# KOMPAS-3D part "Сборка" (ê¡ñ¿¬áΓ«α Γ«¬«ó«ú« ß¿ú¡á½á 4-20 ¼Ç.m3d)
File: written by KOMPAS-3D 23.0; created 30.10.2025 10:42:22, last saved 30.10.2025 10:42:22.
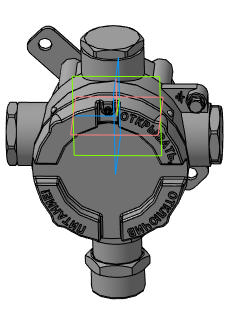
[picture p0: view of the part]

Document properties: Полное имя файла: D:\Users\5322\Documents\КОМПАС\Рабочая\Индикатор токового сигнала 4-20 мА ВУУК ИТС(3-277)\3D\Индикатор токового сигнала 4-20 мА.m3d

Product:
- Part/product: Сборка
    Масса: 1.775804
  - Component [assembly]: Сборка плата  | qty 1  | Масса: 0.276871; source file: Сборка плата.a3d
  - Component [detail]: Стойка  | qty 2  | Материал: ЛС 59-1  ГОСТ 15527-70 (density 8500 kg/m3); Масса: 0.005519; source file: Стойка.m3d
  - Component [detail]: Смотровое стекло  | qty 1  | Материал: Стекло органическое СО-120-А ГОСТ 10667-90 (density 0 kg/m3); source file: Смотровое стекло.m3d
  - Component [detail]: Деталь  | qty 1  | Масса: 0.011643; source file: ..\..\Корпус КРВ\Шильдик-1.m3d
  - Component [standard]: Гайка М4-6H ГОСТ 5915-70  | qty 2  | pos. 1  | Масса: 0.0008; Раздел спецификации: Стандартные изделия
  - Component [standard]: Шпилька М4-6gx22 ГОСТ 22042-76  | qty 1  | pos. 1  | Масса: 0.001706; Раздел спецификации: Стандартные изделия
  - Component [standard]: Шайба C.4.37 ГОСТ 11371-78  | qty 2  | pos. 1  | Материал: АД1 ГОСТ 4784-97 (density 1000 kg/m3); Масса: 0.000299; Раздел спецификации: Стандартные изделия
  - Component [standard]: Шайба 4Л ГОСТ 6402-70  | qty 1  | pos. 1  | Масса: 0.000125; Раздел спецификации: Стандартные изделия
  - Component [standard]: Hexagon socket set screw ISO 4026-М4 x 12-45H  | qty 1  | pos. 1
      Материал: Steel (density 1000 kg/m3)
      Масса: 0.00086
      Раздел спецификации: Стандартные изделия
      Организация: Ascon
      Автор: Constantine
      additional columns: М4 x 12 - 45H
  - Component [standard]: Винт А .М5-6gx8 ГОСТ 17475-80  | qty 1  | pos. 1  | Масса: 0.001391; Раздел спецификации: Стандартные изделия; Автор: Канунников Олег; additional columns: А.М5-6gx8
  - Component [standard]: Винт А.М 5-6g x 8 ГОСТ 17475-80  | qty 1  | pos. 1  | Масса: 0.001391; Раздел спецификации: Стандартные изделия; Автор: Канунников Олег; additional columns: А.М5-6gx8
  - Component [detail]: Кронштейн  | designation СЕНС.741124.906  | qty 1  | Масса: 0.056348; source file: ..\..\Корпус КРВ\Пластина крепежная.m3d
  - Component [standard]: Шайба 5Л ГОСТ 6402-70  | qty 1  | pos. 1  | Масса: 0.000186; Раздел спецификации: Стандартные изделия
  - Component [standard]: Шайба C.5.37 ГОСТ 11371-78  | qty 1  | pos. 1  | Материал: АД1 ГОСТ 4784-97 (density 1000 kg/m3); Масса: 0.00043; Раздел спецификации: Стандартные изделия
  - Component [standard]: Шайба C. 5.37 ГОСТ 11371-78  | qty 1  | pos. 1  | Материал: АД1 ГОСТ 4784-97 (density 1000 kg/m3); Масса: 0.00043; Раздел спецификации: Стандартные изделия; additional columns: C.5.37
  - Component [standard]: Болт DIN 933 - М5 х 16 - А2-70  | qty 1  | pos. 1  | Масса: 0.0036; Раздел спецификации: Стандартные изделия; additional columns: М5-6gx16
  - Component [detail]: Тело_1  | qty 1  | Масса: 0.487789; source file: СЕНС.711322.024-01.m3d
  - Component [detail]: Корпус КРВ  | qty 1  | Материал: Сплав АК7 ГОСТ 1583-93 (density 2700 kg/m3); Масса: 0.428523; source file: ..\..\Корпус КРВ\СЕНС.731142.057.m3d
  - Component [detail]: Заглушка  | designation СЕНС.713141.203  | qty 3  | pos. 2  | Масса: 0.095781; source file: ..\..\Уровнемер СЕНС УМВ\Заглушка - СЕНС.713141.203.m3d
  - Component [assembly]: Кабельный ввод D12-М25-П-1  | designation СЕНС.301536.040-01  | qty 1  | Масса: 0.203696; Автор: setup; source file: ..\..\Дет.кабельных вводов (11-7)\3D\От Савина\1\СЕНС.301536.040 - Кабельный ввод D12-М25-П-1.a3d
- Part/product: Сборка  | designation 01
    Масса: 0.783268
  - Component [assembly]: Сборка плата  | qty 1  | Масса: 0.281051; Вариант геометрического представления: Вариант:1; source file: Сборка плата.a3d
  - Component [detail]: Стойка  | qty 2  | Материал: ЛС 59-1  ГОСТ 15527-70 (density 8500 kg/m3); Масса: 0.005039; Вариант геометрического представления: Вариант:1; source file: Стойка.m3d
  - Component [detail]: Деталь  | qty 1  | Масса: 0.011643; source file: ..\..\Корпус КРВ\Шильдик-1.m3d
  - Component [standard]: Гайка М4-6H ГОСТ 5915-70  | qty 2  | pos. 1  | Масса: 0.0008; Раздел спецификации: Стандартные изделия
  - Component [standard]: Шпилька М4-6gx22 ГОСТ 22042-76  | qty 1  | pos. 1  | Масса: 0.001706; Раздел спецификации: Стандартные изделия
  - Component [standard]: Шайба C.4.37 ГОСТ 11371-78  | qty 2  | pos. 1  | Материал: АД1 ГОСТ 4784-97 (density 1000 kg/m3); Масса: 0.000299; Раздел спецификации: Стандартные изделия
  - Component [standard]: Шайба 4Л ГОСТ 6402-70  | qty 1  | pos. 1  | Масса: 0.000125; Раздел спецификации: Стандартные изделия
  - Component [standard]: Hexagon socket set screw ISO 4026-М4 x 12-45H  | qty 1  | pos. 1
      Материал: Steel (density 1000 kg/m3)
      Масса: 0.00086
      Раздел спецификации: Стандартные изделия
      Организация: Ascon
      Автор: Constantine
      additional columns: М4 x 12 - 45H
  - Component [standard]: Шайба 5Л ГОСТ 6402-70  | qty 1  | pos. 1  | Масса: 0.000186; Раздел спецификации: Стандартные изделия
  - Component [standard]: Шайба C.5.37 ГОСТ 11371-78  | qty 1  | pos. 1  | Материал: АД1 ГОСТ 4784-97 (density 1000 kg/m3); Масса: 0.00043; Раздел спецификации: Стандартные изделия
  - Component [standard]: Шайба C. 5.37 ГОСТ 11371-78  | qty 1  | pos. 1  | Материал: АД1 ГОСТ 4784-97 (density 1000 kg/m3); Масса: 0.00043; Раздел спецификации: Стандартные изделия; additional columns: C.5.37
  - Component [standard]: Болт DIN 933 - М5 х 16 - А2-70  | qty 1  | pos. 1  | Масса: 0.0036; Раздел спецификации: Стандартные изделия; additional columns: М5-6gx16
  - Component [detail]: Корпус КРВ  | qty 1  | Материал: Сплав АК7 ГОСТ 1583-93 (density 2700 kg/m3); Масса: 0.428523; source file: ..\..\Корпус КРВ\СЕНС.731142.057.m3d
  - Component [assembly]: Кабельный ввод D12-М25-П-1  | designation СЕНС.301536.040-01  | qty 2  | pos. 2  | Масса: 0.203696; Автор: setup; source file: ..\..\Дет.кабельных вводов (11-7)\3D\От Савина\1\СЕНС.301536.040 - Кабельный ввод D12-М25-П-1.a3d
  - Component [detail]: Заглушка  | designation СЕНС.713141.203  | qty 2  | Масса: 0.095781; source file: ..\..\Уровнемер СЕНС УМВ\Заглушка - СЕНС.713141.203.m3d
  - Component [assembly]: Крышка  | designation СЕНС.301191.325СБ  | qty 1  | pos. 3  | Масса: 0.191982; source file: Крышка - СЕНС.301191.325-02 СБ.a3d
- Part/product: Сборка
    Масса: 1.481834
    Вариант геометрического представления: Вариант:1
- Part/product: Сборка
    Масса: 0.761491
    Вариант геометрического представления: Вариант:2
  - Component [assembly]: Сборка плата  | qty 1  | Масса: 0.276871; source file: Сборка плата.a3d
  - Component [detail]: Стойка  | qty 2  | Материал: ЛС 59-1  ГОСТ 15527-70 (density 8500 kg/m3); Масса: 0.005519; source file: Стойка.m3d
  - Component [detail]: Деталь  | qty 1  | Масса: 0.011643; source file: ..\..\Корпус КРВ\Шильдик-1.m3d
  - Component [standard]: Гайка М4-6H ГОСТ 5915-70  | qty 2  | pos. 1  | Масса: 0.0008; Раздел спецификации: Стандартные изделия
  - Component [standard]: Шпилька М4-6gx22 ГОСТ 22042-76  | qty 1  | pos. 1  | Масса: 0.001706; Раздел спецификации: Стандартные изделия
  - Component [standard]: Шайба C.4.37 ГОСТ 11371-78  | qty 2  | pos. 1  | Материал: АД1 ГОСТ 4784-97 (density 1000 kg/m3); Масса: 0.000299; Раздел спецификации: Стандартные изделия
  - Component [standard]: Шайба 4Л ГОСТ 6402-70  | qty 1  | pos. 1  | Масса: 0.000125; Раздел спецификации: Стандартные изделия
  - Component [standard]: Hexagon socket set screw ISO 4026-М4 x 12-45H  | qty 1  | pos. 1
      Материал: Steel (density 1000 kg/m3)
      Масса: 0.00086
      Раздел спецификации: Стандартные изделия
      Организация: Ascon
      Автор: Constantine
      additional columns: М4 x 12 - 45H
  - Component [standard]: Винт А .М5-6gx8 ГОСТ 17475-80  | qty 1  | pos. 1  | Масса: 0.001391; Раздел спецификации: Стандартные изделия; Автор: Канунников Олег; additional columns: А.М5-6gx8
  - Component [standard]: Винт А.М 5-6g x 8 ГОСТ 17475-80  | qty 1  | pos. 1  | Масса: 0.001391; Раздел спецификации: Стандартные изделия; Автор: Канунников Олег; additional columns: А.М5-6gx8
  - Component [detail]: Кронштейн  | designation СЕНС.741124.906  | qty 1  | Масса: 0.056348; source file: ..\..\Корпус КРВ\Пластина крепежная.m3d
  - Component [standard]: Шайба 5Л ГОСТ 6402-70  | qty 1  | pos. 1  | Масса: 0.000186; Раздел спецификации: Стандартные изделия
  - Component [standard]: Шайба C.5.37 ГОСТ 11371-78  | qty 1  | pos. 1  | Материал: АД1 ГОСТ 4784-97 (density 1000 kg/m3); Масса: 0.00043; Раздел спецификации: Стандартные изделия
  - Component [standard]: Шайба C. 5.37 ГОСТ 11371-78  | qty 1  | pos. 1  | Материал: АД1 ГОСТ 4784-97 (density 1000 kg/m3); Масса: 0.00043; Раздел спецификации: Стандартные изделия; additional columns: C.5.37
  - Component [standard]: Болт DIN 933 - М5 х 16 - А2-70  | qty 1  | pos. 1  | Масса: 0.0036; Раздел спецификации: Стандартные изделия; additional columns: М5-6gx16
  - Component [detail]: Корпус КРВ  | qty 1  | Материал: Сплав АК7 ГОСТ 1583-93 (density 2700 kg/m3); Масса: 0.428523; source file: ..\..\Корпус КРВ\СЕНС.731142.057.m3d
  - Component [detail]: Заглушка  | designation СЕНС.713141.203  | qty 3  | pos. 2  | Масса: 0.095781; source file: ..\..\Уровнемер СЕНС УМВ\Заглушка - СЕНС.713141.203.m3d
  - Component [assembly]: Кабельный ввод D12-М25-П-1  | designation СЕНС.301536.040-01  | qty 1  | Масса: 0.203696; Автор: setup; source file: ..\..\Дет.кабельных вводов (11-7)\3D\От Савина\1\СЕНС.301536.040 - Кабельный ввод D12-М25-П-1.a3d
  - Component [assembly]: Крышка  | designation СЕНС.301191.388  | qty 1  | pos. 4  | Масса: 0.218835; Организация: Ã Å¾Ã Å¾Ã Å¾ Ã Â Ã Å¸Ã Å¸ "Ã Â¡Ã â€¢Ã Â Ã Â¡Ã Å¾Ã Â "; Автор: sensor-wa; source file: СЕНС.301191.388 - Крышка.a3d

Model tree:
1. Операция без истории:1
